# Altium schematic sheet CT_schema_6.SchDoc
size 254 x 194 mm
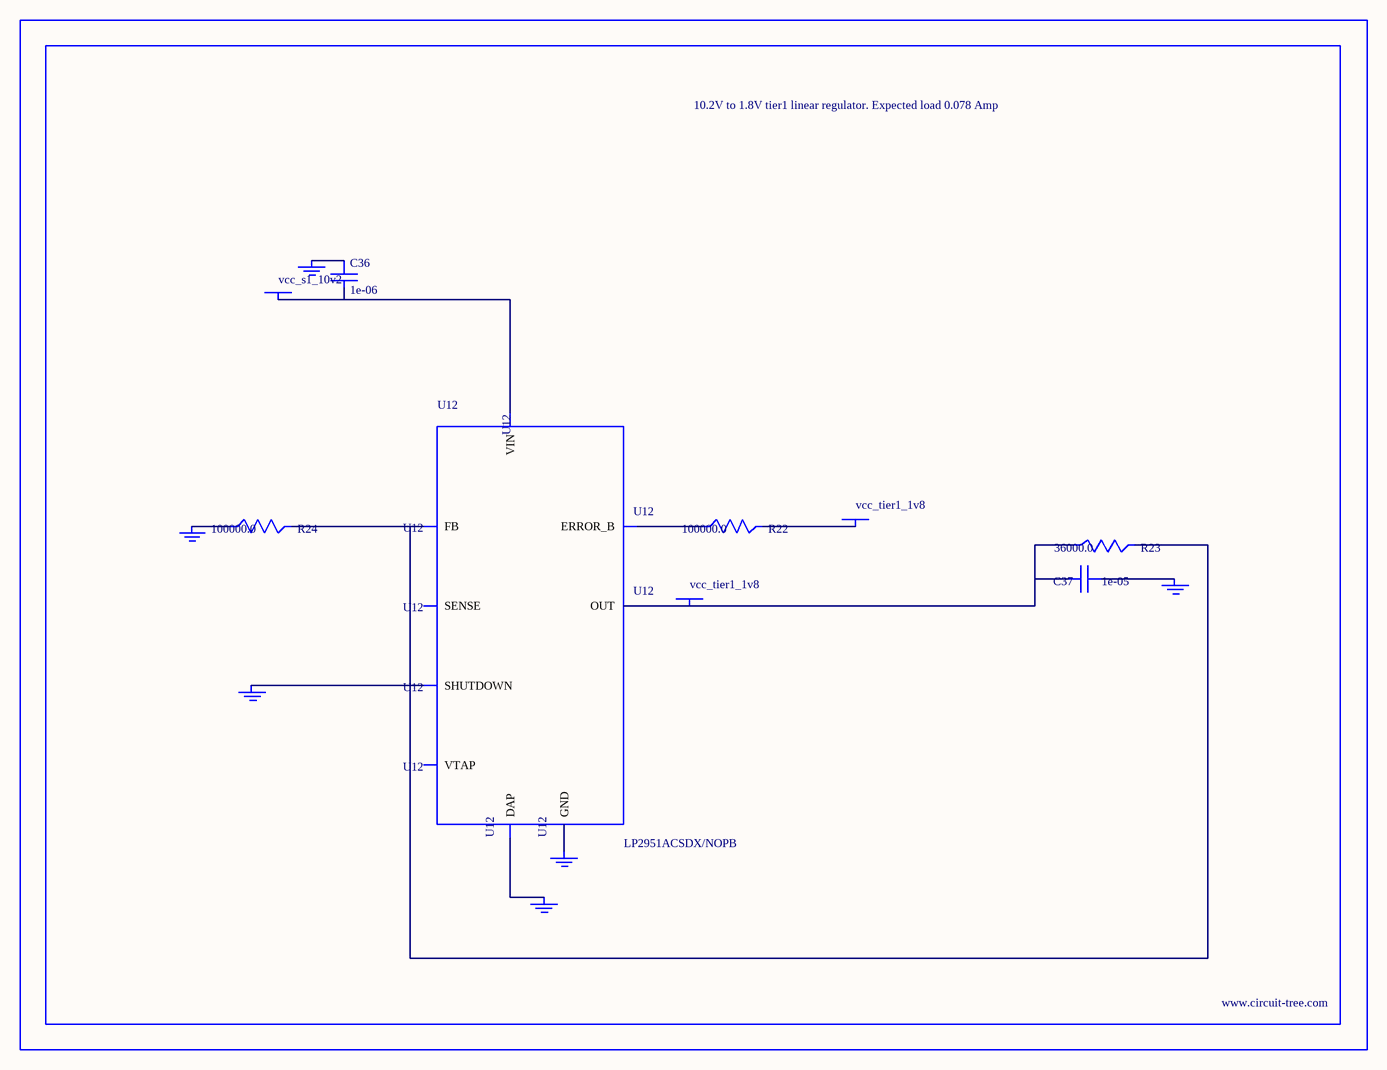
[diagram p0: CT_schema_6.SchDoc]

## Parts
BORDER5  (no value)
C36  1e-06  [C0603]
C37  1e-05  [C0805]
GND_INSTANCE_5_0  (no value)
GND_INSTANCE_5_1  (no value)
GND_INSTANCE_5_2  (no value)
GND_INSTANCE_5_3  (no value)
GND_INSTANCE_5_4  (no value)
GND_INSTANCE_5_5  (no value)
POWER_INSTANCE_5_0  vcc_tier1_1v8
POWER_INSTANCE_5_1  vcc_s1_10v2
POWER_INSTANCE_5_2  vcc_tier1_1v8
R22  100000.0  [R0603]
R23  36000.0  [R0603]
R24  100000.0  [R0603]
U12  LP2951ACSDX/NOPB  [WSON-8]

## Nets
NetC36_1: C36.1 GND_INSTANCE_5_3.0(GND)
NetC36_2: C36.2 POWER_INSTANCE_5_1.0(PWR) U12.8(VIN)
NetC37_1: C37.1 GND_INSTANCE_5_0.0(GND)
NetC37_2: C37.2 POWER_INSTANCE_5_2.0(PWR) R23.1 U12.1(OUT)
NetGND_INSTANCE_5_1_0: GND_INSTANCE_5_1.0(GND) U12.3(SHUTDOWN)
NetGND_INSTANCE_5_2_0: GND_INSTANCE_5_2.0(GND) R24.1
NetGND_INSTANCE_5_4_0: GND_INSTANCE_5_4.0(GND) U12.PAD(DAP)
NetGND_INSTANCE_5_5_0: GND_INSTANCE_5_5.0(GND) U12.4(GND)
NetPOWER_INSTANCE_5_0_0: POWER_INSTANCE_5_0.0(PWR) R22.2
NetR22_1: R22.1 U12.5(ERROR_B)
NetR23_2: R23.2 R24.2 U12.7(FB)

Not connected (* = marked no-connect by the designer): U12 2(SENSE) 6(VTAP)

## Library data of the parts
BORDER5 = BORDER_PAGE5
C36 = C0603C105K3RACTU
C37 = GRM219R60J106ME19D
GND_INSTANCE_5_0-GND_INSTANCE_5_5 = GND
POWER_INSTANCE_5_0-POWER_INSTANCE_5_2 = PWR
R22 R24 = RC0603JR-07100KL
R23 = RC0603JR-0736KL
